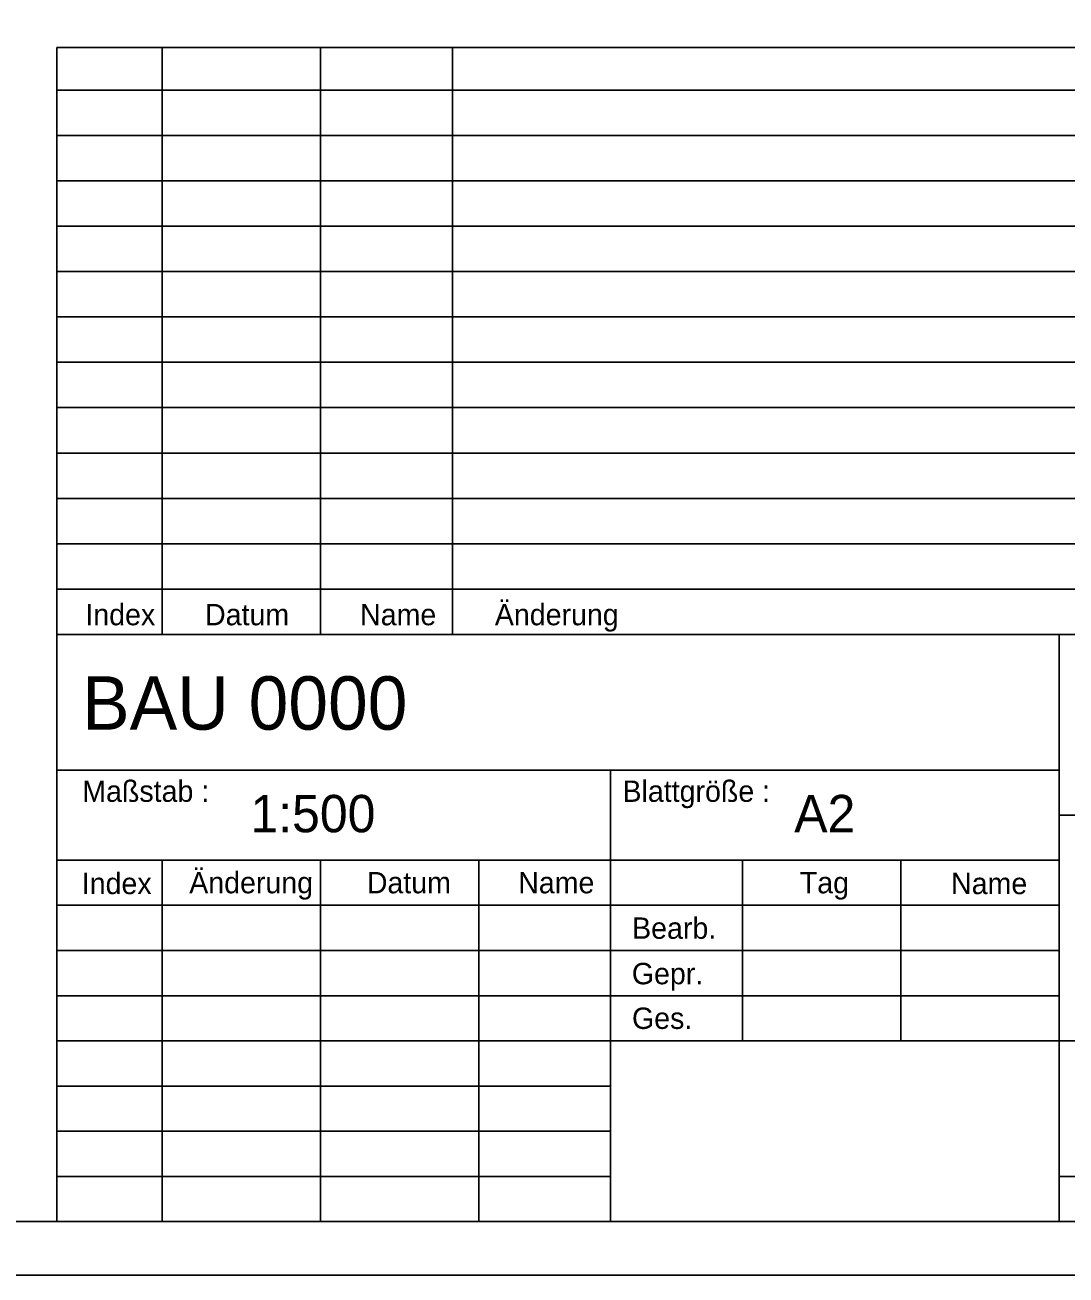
# Model space of a CAD drawing. Extents: x 0 to 297, y 0 to 210.
# Drawn here: x 204.1 to 252.8, y 0 to 58.5 of the extents above; entities that cross this region are included whole.
import ezdxf

# ---------------------------------------------------------------- set-up
doc = ezdxf.new("R2010")
doc.units = 0
doc.layers.add('90_Plankopf', color=7, linetype='Continuous')

msp = doc.modelspace()

# ---------------------------------------------------------------- linework, layer by layer
at = {"layer": '90_Plankopf'}
for p, q in [((205.56, 29.995), (205.56, 57.49)), ((205.56, 57.49), (294.5, 57.49)), ((210.501, 29.995), (210.501, 57.49)), ((217.913, 29.995), (217.913, 57.49)), ((224.09, 29.995), (224.09, 57.49)), ((205.56, 55.495), (294.5, 55.495)), ((205.56, 53.37), (294.5, 53.37)), ((205.56, 51.245), (294.5, 51.245)), ((205.56, 49.12), (294.5, 49.12)), ((205.56, 46.995), (294.5, 46.995)), ((205.56, 44.87), (294.5, 44.87)), ((205.56, 42.745), (294.5, 42.745)), ((205.56, 40.62), (294.5, 40.62)), ((205.56, 38.495), (294.5, 38.495)), ((205.56, 36.37), (294.5, 36.37)), ((205.56, 34.245), (294.5, 34.245)), ((205.56, 32.12), (294.5, 32.12)), ((205.56, 29.995), (294.5, 29.995)), ((205.56, 2.5), (205.56, 29.995)), ((205.56, 29.995), (294.5, 29.995)), ((252.501, 2.5), (252.501, 29.995)), ((205.56, 23.65), (252.501, 23.65)), ((231.501, 2.5), (231.501, 23.65)), ((252.501, 21.535), (294.5, 21.535)), ((205.56, 19.435), (252.501, 19.435)), ((210.501, 19.42), (210.501, 2.5)), ((217.913, 2.5), (217.913, 19.42)), ((225.325, 2.5), (225.325, 19.42)), ((237.677, 19.42), (237.677, 10.96)), ((245.089, 10.96), (245.089, 19.42)), ((205.56, 17.315), (252.501, 17.315)), ((205.56, 15.19), (252.501, 15.19)), ((205.56, 13.075), (252.501, 13.075)), ((205.56, 10.96), (252.501, 10.96)), ((205.56, 10.96), (252.501, 10.96)), ((231.501, 10.96), (252.501, 10.96)), ((252.501, 10.96), (294.5, 10.96)), ((231.501, 8.845), (205.56, 8.845)), ((231.501, 6.73), (205.56, 6.73)), ((205.56, 4.615), (231.501, 4.615)), ((252.501, 4.615), (294.5, 4.615)), ((294.5, 2.5), (205.56, 2.5)), ((205.56, 2.5), (231.501, 2.5)), ((211.4, 2.5), (294.5, 2.5)), ((211.4, 2.5), (294.5, 2.5))]:
    msp.add_line(p, q, dxfattribs=at)
for points in [[(0, 0), (297, 0), (297, 210), (0, 210)], [(12.5, 207.5), (294.5, 207.5), (294.5, 2.5), (12.5, 2.5)]]:
    msp.add_lwpolyline(points, close=True, dxfattribs=at)

# ---------------------------------------------------------------- texts
for s, height, p in [('Änderung', 1, (226.079, 30.428)), ('Index', 1, (206.902, 30.428)), ('Datum', 1, (212.507, 30.428)), ('Name', 1, (219.769, 30.428)), ('BAU 0000      ', 2.5, (206.745, 25.538)), ('Maßstab :', 1, (206.758, 22.158)), ('Blattgröße :', 0.99995, (232.058, 22.158)), ('1:500    ', 1.75, (214.631, 20.734)), ('A2       ', 1.75, (240.1, 20.734)), ('Index', 1, (206.734, 17.837)), ('Änderung', 1, (211.767, 17.875)), ('Datum', 1, (220.084, 17.875)), ('Name', 1, (227.174, 17.875)), ('Tag', 1, (240.362, 17.875)), ('Name', 1, (247.446, 17.837)), ('Bearb.', 1, (232.507, 15.745)), ('Gepr.', 1, (232.495, 13.615)), ('Ges.', 1, (232.502, 11.524))]:
    msp.add_text(s, height=height, dxfattribs=at).set_placement(p)

doc.saveas('drawing.dxf')
